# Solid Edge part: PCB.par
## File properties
Author: hhakima
Template: Normal.par
Last saved by: hhakima
Revision: 4
Application: Solid Edge
Density: 1300.000 kg/m^3
Accuracy: 0.990
Material: Epoxy, cast rigid
Face Style: White
Fill Style: ANSI34(Plastic)
Virtual Style: Ionomer resin
Coef. of Thermal Exp: 5.9e-05
Thermal Conductivity: 2.1
Specific Heat: 0.0
Modulus of Elasticity: 3102640650.0
Poission's Ratio: 0.37
Yield Stress: 65500191.5
Ultimate Stress: 0.0
Elongation: 0.0
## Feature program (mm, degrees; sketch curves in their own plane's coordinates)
sketch for "unnamed Protrusion 1" plane through (0, 0, 0) normal (0, 0, 1) x-axis (1, 0, 0)
  line (-44.0318, 26.4059) -> (-44.0318, -18.5941)
  line (-44.0318, -18.5941) -> (-6.0318, -18.5941)
  line (-6.0318, -18.5941) -> (-6.0318, 26.4059)
  line (-6.0318, 26.4059) -> (-44.0318, 26.4059)
extrude "unnamed Protrusion 1" add finite 1.5 along -normal
sketch for "Hole_1" plane through (-24.0318, 1.4059, 0) normal (0, 0, 1) x-axis (1, 0, 0)
  hole centre (15.8, 22.8) bore radius 0.9
hole "Hole_1" diameter 1.8 through
sketch for "unnamed Hole 1" plane through (-24.0318, 1.4059, 0) normal (0, 0, 1) x-axis (1, 0, 0)
  hole centre (-17.8, -17.8) bore radius 0.9
  dimension (linear) = 17.8
hole "unnamed Hole 1" through
pattern "unnamed Pattern 1" of "Hole_1", "unnamed Hole 1"
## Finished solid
Body 1: solid body, 8 faces, 16 edges, 8 vertices.
  Faces by surface: plane 6, cylinder 2
  Edges by curve: line 12, circle 4
Bounding box of the edges (mm): 38.000 x 45.000 x 1.500, from (-44.0318, -18.5941, -1.5) to (-6.0318, 26.4059, 0).
Cylindrical faces by radius (mm): R0.9 x2
Planar faces by outward normal: +x 1, +y 1, +z 1, -x 1, -y 1, -z 1
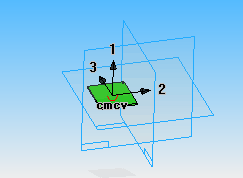
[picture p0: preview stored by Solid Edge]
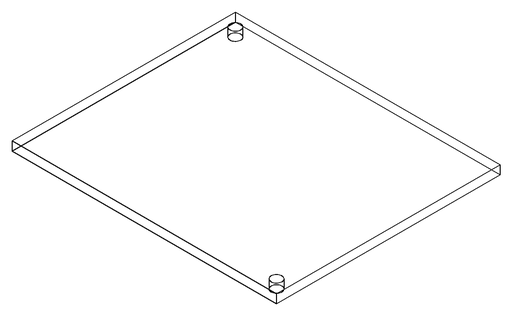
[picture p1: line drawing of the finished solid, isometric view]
